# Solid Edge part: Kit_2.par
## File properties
Sűrűség: 0,000 kg/m^3
Pontosság: 0,990
Author: ahadarics
Last saved by: ahadarics
Revision: 76
Username: ahadarics
Dokumentum tartalom típus: 0
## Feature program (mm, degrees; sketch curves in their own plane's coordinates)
base feature "unnamed BaseFeature 1"
sketch for "Furat_1" plane through (0, 13.5, 0) normal (0, 1, 0) x-axis (0, 0, 1)
  hole centre (-0.25, 0) bore radius 4.283
hole "Furat_1" nominal diameter 9.728 finite  ThreadDepth = 7.5 mm
chamfer "Letörés_1" setback 0.7
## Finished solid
Body 1: solid body, 20 faces, 26 edges, 7 vertices.
  Faces by surface: cylinder 8, cone 6, plane 6
  Edges by curve: circle 18, line 5, spline 2, intersection 1
Bounding box of the edges (mm): 30.000 x 28.500 x 23.500, from (-15, -15, -15.75) to (15, 13.5, 7.75).
Cylindrical faces by radius (mm): R1 x1, R2.5 x1, R4.28 x1, R4.283 x1, R11.45 x1, R12.5 x1, R13.5 x1, R15 x1
Conical faces (half-angle, radius in mm at the cone's reference point): 30 deg R12.4134 x1, 45 deg R4.983 x1, 45 deg R11.975 x1, 45 deg R14.75 x1, 59 deg R1.25 x1, 59 deg R2.1415 x1
Planar faces by outward normal: +y 2, +z 1, -z 3
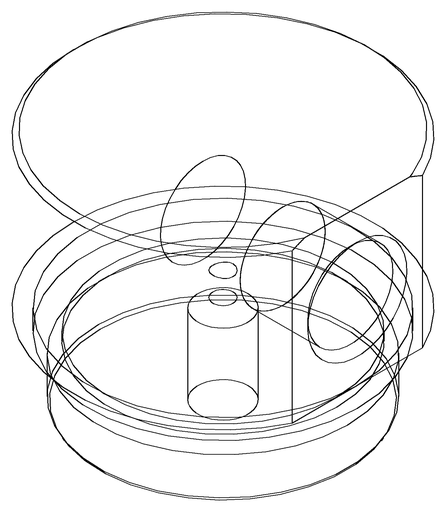
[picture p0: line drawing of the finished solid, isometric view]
